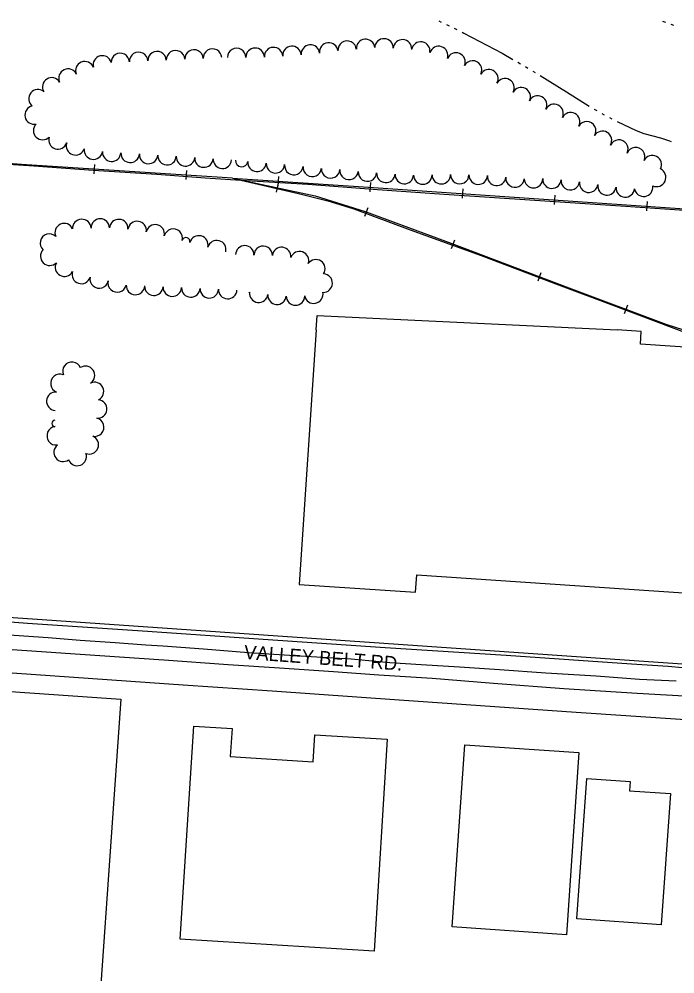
# Model space of a CAD drawing. Extents: x -25029 to 2274964, y -81170 to 687028.
# Drawn here: x -8354 to -7644, y -65446 to -64412 of the extents above; entities that cross this region are included whole.
import ezdxf

# ---------------------------------------------------------------- set-up
doc = ezdxf.new("R2010")
doc.units = 0
for name, color, linetype in [('81911BEA - RW_X_Fee_RW', 7, 'Continuous'), ('BLDG', 7, 'Continuous'), ('GE_X_CL_2000', 7, 'Continuous'), ('PV_X_EOP', 7, 'Continuous'), ('RD_X_RR_1', 7, 'Continuous'), ('ROAD-NAME', 7, 'Continuous'), ('RR', 7, 'Continuous'), ('TREES', 7, 'Continuous'), ('WATER', 7, 'Continuous')]:
    doc.layers.add(name, color=color, linetype=linetype)

msp = doc.modelspace()

# ---------------------------------------------------------------- linework, layer by layer
at = {"layer": '81911BEA - RW_X_Fee_RW'}
for points in [[(-7307.6, -65121.1), (-7510.8, -65119.2), (-8360.2, -65060.1), (-8519.4, -65049), (-8521.8, -65048.8), (-8532.9, -65048.1), (-8559.7, -65046.2), (-8580.6, -65044.7)], [(-7519.6, -65178.7), (-7632.7, -65170.8), (-7750.8, -65162.6), (-7942.6, -65149.3), (-8079.8, -65139.7), (-8176.4, -65133), (-8459.5, -65113.3), (-8523.4, -65108.9), (-8584.7, -65104.6)]]:
    msp.add_lwpolyline(points, dxfattribs=at)
at = {"layer": 'BLDG'}
msp.add_line((-8032.2, -64748.4), (-8050.8, -65024.1), dxfattribs=at)
for points in [[(-8032.2, -64748.4), (-8031.1, -64732.9), (-7706.6, -64748.4)], [(-8050.8, -65024.1), (-7924.8, -65032.6), (-7923.5, -65013.7), (-7549.1, -65039), (-7531.2, -64774.2), (-7681.4, -64764), (-7680.5, -64750.1), (-7706.6, -64748.4)]]:
    msp.add_lwpolyline(points, dxfattribs=at)
for points in [[(-8417, -65456.8), (-8407.3, -65318.9), (-8434.6, -65311), (-8423.7, -65154.7), (-8395.8, -65156.7), (-8394.5, -65137.8), (-8243.7, -65148.4), (-8266.1, -65467.4)], [(-8123.4, -65180), (-8125.3, -65210.5), (-8035.7, -65216.1), (-8033.8, -65186.9), (-7955.3, -65191.8), (-7969.7, -65421.3), (-8179.4, -65408.2), (-8164.9, -65177.4)], [(-7748, -65206.2), (-7761.5, -65403.4), (-7885, -65394.9), (-7871.4, -65197.7)], [(-7692.6, -65237.4), (-7693.3, -65247.4), (-7648.9, -65250.5), (-7659, -65392.7), (-7750.2, -65386.2), (-7739.4, -65234.1)]]:
    msp.add_lwpolyline(points, close=True, dxfattribs=at)
at = {"layer": 'GE_X_CL_2000'}
msp.add_lwpolyline([(-8369.6, -65078.3), (-8322.3, -65081.6), (-8287.8, -65084.4), (-8250, -65086.8), (-8216.5, -65089.4), (-8198.4, -65090.7), (-8154.3, -65093.8), (-8105.5, -65097.7), (-8067.1, -65100.5), (-8025.7, -65102.7), (-7994.6, -65104.7), (-7952.6, -65108.5), (-7918.7, -65110.9), (-7877.1, -65113.3), (-7834, -65116.2), (-7783.6, -65119.7), (-7729.1, -65123.2), (-7682.5, -65126.5), (-7642.7, -65128.3)], dxfattribs=at)
at = {"layer": 'PV_X_EOP'}
for p, q in [((-8344.8, -65066.4), (-8529, -65052.9)), ((-8215, -65075), (-8344.8, -65066.4)), ((-8089.6, -65083.7), (-8215, -65075)), ((-7957.8, -65092.8), (-8089.6, -65083.7)), ((-7826.7, -65101.1), (-7957.8, -65092.8)), ((-7691, -65110.3), (-7826.7, -65101.1)), ((-7651.2, -65113.1), (-7691, -65110.3)), ((-7602.6, -65117.2), (-7651.2, -65113.1))]:
    msp.add_line(p, q, dxfattribs=at)
msp.add_lwpolyline([(-8403.7, -65091.6), (-8287.8, -65099.6), (-8197.2, -65105.9), (-8127.7, -65110.9), (-8072.1, -65114.5), (-8013.6, -65118.5), (-7964.6, -65122), (-7906.9, -65125.6), (-7840.2, -65131.1), (-7764.4, -65136.6), (-7684.9, -65142), (-7621.5, -65145.5), (-7559.7, -65149.8), (-7484.3, -65155.2), (-7432.2, -65158.5), (-7388, -65161), (-7351.4, -65163.6), (-7305.8, -65165.9), (-7268.4, -65168.2), (-7247.9, -65170.1), (-7235.1, -65171.2)], dxfattribs=at)
at = {"layer": 'RD_X_RR_1'}
for points in [[(-9225.8, -64451.8), (-9193.7, -64461.8), (-9157.9, -64472.5), (-9119.3, -64483.5), (-9078.6, -64494.1), (-9033, -64503.8), (-8990.6, -64512), (-8939.1, -64520.7), (-8894.3, -64527.3), (-8849.3, -64533), (-8810.1, -64537.3), (-8760.6, -64541.9), (-8695, -64546.3), (-8649.5, -64549.4), (-8583.3, -64553.9), (-8521.8, -64558.4), (-8454.6, -64562.9), (-8388.1, -64567.8), (-8337.8, -64570.9), (-8273.7, -64575.7), (-8204.8, -64580), (-8152.5, -64583.8), (-8113.8, -64586.5)], [(-8113.8, -64586.5), (-8051.3, -64600.7), (-8019.8, -64608.7), (-7991.6, -64617.5), (-7930.5, -64640), (-7853.7, -64667.9), (-7775.7, -64697.6), (-7702.6, -64725), (-7628.8, -64752.8)], [(-8113.8, -64586.5), (-8041.5, -64590.9), (-7966, -64596.5), (-7893.6, -64601.5), (-7702.8, -64614.3), (-7638.9, -64618.5), (-7582.9, -64622.4), (-7516.3, -64627), (-7442.7, -64632.1), (-7377.5, -64635.9), (-7324.7, -64639.8), (-7243, -64646.2), (-7159.3, -64651.8)]]:
    msp.add_lwpolyline(points, dxfattribs=at)
at = {"layer": 'RR'}
for p, q in [((-8272.4, -64569.4), (-8273.1, -64579.4)), ((-8172.6, -64575.9), (-8173.3, -64585.8)), ((-8075.2, -64599.4), (-8073.1, -64589.6)), ((-8073.5, -64592.4), (-8072.8, -64582.4)), ((-7973.7, -64599.1), (-7973, -64589.1)), ((-7873.9, -64605.9), (-7873.3, -64595.9)), ((-7774.2, -64612.7), (-7773.5, -64602.7)), ((-7674.4, -64619.5), (-7673.7, -64609.6)), ((-7979.5, -64625.5), (-7976, -64616.1)), ((-7885.8, -64660.3), (-7882.3, -64651)), ((-7792.2, -64695.5), (-7788.7, -64686.2)), ((-7698.6, -64730.7), (-7695.1, -64721.4))]:
    msp.add_line(p, q, dxfattribs=at)
for points in [[(-8123, -64584.1), (-8351.4, -64569.3), (-8550.3, -64554.7), (-8738.4, -64541.7), (-8817.7, -64534.7), (-8870.3, -64529.1), (-8945.3, -64518.6), (-9004, -64508.1), (-9104.9, -64485.3), (-9189, -64461.6), (-9278.4, -64432.1), (-9377.8, -64393.2), (-9451.7, -64359.8), (-9555.4, -64306.9), (-9661.5, -64244.3), (-9748.4, -64184.6)], [(-8123, -64584.1), (-7975.6, -64593.9), (-7475.4, -64628.1), (-7223.8, -64646.2), (-7086.9, -64655.4), (-6939.2, -64672.5), (-6864.5, -64686.5), (-6810.8, -64699.4), (-6730.7, -64721.1), (-6647, -64748.4)], [(-8123, -64584.1), (-8033.4, -64603.2), (-7979.4, -64620.2), (-7885.4, -64655.1), (-7758.7, -64702.8), (-7653.9, -64742.2), (-7634.7, -64748.4)]]:
    msp.add_lwpolyline(points, dxfattribs=at)
at = {"layer": 'TREES'}
for centre, radius, start, end in [((-7998.8, -64445.6), 10, 5.0361, 185.0361), ((-7978.8, -64443.8), 10, 5.0304, 185.0304), ((-7958.9, -64443.2), 10, 358.3471, 178.3471), ((-7938.9, -64444.2), 10, 356.1464, 176.1464), ((-8184.5, -64456), 10, 2.5902, 182.5902), ((-8164.5, -64455.1), 10, 2.5902, 182.5902), ((-8144.5, -64454.2), 10, 2.5902, 182.5902), ((-8118.4, -64453.5), 10, 359.5944, 179.5944), ((-8098.4, -64453.3), 10, 1.2867, 181.2867), ((-8078.4, -64452.6), 10, 3.2117, 183.2117), ((-8058.5, -64451.3), 10, 3.8432, 183.8432), ((-8038.5, -64449.7), 10, 5.3088, 185.3088), ((-8018.6, -64447.6), 10, 6.7123, 186.7123), ((-7919.1, -64446.6), 10, 350.3329, 170.3329), ((-7899.7, -64451.4), 10, 341.4546, 161.4546), ((-8263.8, -64461.6), 10, 14.2942, 194.2942), ((-8244.3, -64458.7), 9.82, 2.5902, 182.5902), ((-8224.5, -64457.8), 10, 2.5902, 182.5902), ((-8204.5, -64456.9), 10, 2.5902, 182.5902), ((-7881, -64458.5), 10, 337.0983, 157.0983), ((-8301, -64475.9), 10, 25.0618, 205.0618), ((-8282.7, -64467.9), 10, 22.3729, 202.3729), ((-7863, -64467.1), 10, 331.9484, 151.9484), ((-7845.4, -64476.6), 10, 331.2605, 151.2605), ((-8318.6, -64485.4), 10, 31.463, 211.463), ((-7827.9, -64486.3), 10, 330.538, 150.538), ((-7810.4, -64495.9), 10, 332.4164, 152.4164), ((-8333.4, -64498.3), 10, 50.8821, 230.8821), ((-7792.6, -64505.1), 10, 332.6236, 152.6236), ((-8337.6, -64515.9), 10, 102.1834, 282.1834), ((-7774.8, -64514.1), 10, 333.8801, 153.8801), ((-7756.9, -64523.2), 10, 332.2957, 152.2957), ((-8328.4, -64532.7), 10, 135.4354, 315.4354), ((-7739.5, -64533), 10, 328.6459, 148.6459), ((-7722.4, -64543.3), 10, 329.4119, 149.4119), ((-8311.8, -64542.9), 10, 161.4726, 341.4726), ((-8292.8, -64549.2), 10, 161.684, 341.684), ((-7704.7, -64552.7), 10, 334.461, 154.461), ((-8273.4, -64553.9), 10, 171.0113, 351.0113), ((-8253.6, -64556.1), 10, 176.3288, 356.3288), ((-8233.6, -64557.4), 10, 176.3288, 356.3288), ((-8213.7, -64558.6), 10, 176.3288, 356.3288), ((-8193.7, -64559.9), 10, 176.3288, 356.3288), ((-7686.5, -64561), 10, 336.6182, 156.6182), ((-7668.5, -64569.6), 10, 332.0775, 152.0775), ((-8173.7, -64561.2), 10, 176.3288, 356.3288), ((-8153.8, -64562.5), 10, 176.3288, 356.3288), ((-8133.8, -64563.8), 10, 176.3288, 356.3288), ((-8112.9, -64565.4), 6.63, 173.7911, 353.7911), ((-8096.3, -64567.1), 10, 174.9216, 354.9216), ((-8076.4, -64568.7), 10, 175.4854, 355.4854), ((-8056.5, -64570.6), 10, 173.7291, 353.7291), ((-8036.6, -64572.6), 10, 174.66, 354.66), ((-8016.6, -64574.2), 10, 176.5368, 356.5368), ((-7996.7, -64575.8), 10, 174.0214, 354.0214), ((-7976.8, -64577.6), 10, 175.6263, 355.6263), ((-7956.9, -64579.1), 10, 175.9516, 355.9516), ((-7936.9, -64580.3), 10, 176.8725, 356.8725), ((-7896.9, -64580.5), 10, 181.5983, 1.5983), ((-7876.9, -64580.4), 10, 179.0565, 359.0565), ((-7663.8, -64583.4), 10, 245.4744, 65.4744), ((-7916.9, -64580.8), 10, 180.3727, 0.3727), ((-7856.9, -64581), 10, 177.4044, 357.4044), ((-7837, -64582.3), 10, 174.746, 354.746), ((-7817.1, -64584.1), 10, 175.0287, 355.0287), ((-7797.1, -64584.8), 10, 180.7976, 0.7976), ((-7777.1, -64585.3), 10, 176.4179, 356.4179), ((-7757.2, -64587), 10, 173.8861, 353.8861), ((-7737.4, -64589.7), 10, 170.9041, 350.9041), ((-7717.6, -64592.6), 10, 172.2738, 352.2738), ((-7697.7, -64594.8), 10, 175.2372, 355.2372), ((-7677.9, -64594.1), 10, 188.8934, 8.8934), ((-8286, -64638.7), 10, 2.5263, 182.5263), ((-8266, -64638.2), 10, 0.2184, 180.2184), ((-8246, -64638.8), 10, 356.3463, 176.3463), ((-8226.1, -64640.9), 10, 351.6433, 171.6433), ((-8305.1, -64643.2), 10, 24.2284, 204.2284), ((-8206.5, -64644.5), 10, 347.4226, 167.4226), ((-8187, -64649.2), 10, 345.383, 165.383), ((-8321.1, -64654.6), 10, 46.567, 226.567), ((-8173.2, -64652.9), 4.34, 345.2306, 165.2306), ((-8159.3, -64656.5), 10, 345.2306, 165.2306), ((-8139.9, -64661.6), 10, 345.2306, 165.2306), ((-8320.7, -64668.8), 10, 135.9881, 315.9881), ((-8109.6, -64667.2), 10, 358.6295, 178.6295), ((-8089.6, -64667.7), 10, 358.8178, 178.8178), ((-8069.7, -64669), 10, 353.3106, 173.3106), ((-8050.3, -64673.5), 10, 340.7394, 160.7394), ((-8032.6, -64682.3), 10, 326.3804, 146.3804), ((-8304.8, -64680.6), 10, 150.9378, 330.9378), ((-8286.6, -64688.5), 10, 162.241, 342.241), ((-8267.2, -64693.4), 10, 169.2198, 349.2198), ((-8024.7, -64697.9), 10, 267.6682, 87.6682), ((-8247.7, -64697.7), 10, 166.4408, 346.4408), ((-8227.9, -64700.4), 10, 177.4459, 357.4459), ((-8208, -64701.3), 10, 177.4459, 357.4459), ((-8188, -64702.2), 10, 177.4459, 357.4459), ((-8168, -64703.1), 10, 177.4459, 357.4459), ((-8148, -64704), 10, 177.4459, 357.4459), ((-8128, -64704.9), 10, 177.4459, 357.4459), ((-8104.8, -64707.6), 0.364, 172.6183, 352.6183), ((-8094.5, -64708.9), 10, 172.7016, 352.7016), ((-8074.6, -64711), 10, 175.0842, 355.0842), ((-8054.7, -64711.8), 10, 180.2176, 0.2176), ((-8034.9, -64709.8), 10, 191.4089, 11.4089), ((-8296.7, -64793.3), 10, 22.8898, 202.8898), ((-8309.7, -64806.5), 10, 68.3483, 248.3483), ((-8282, -64797.7), 10, 303.6107, 123.6107), ((-8272.2, -64815.1), 10, 295.1862, 115.1862), ((-8314.1, -64825.8), 10, 85.3645, 265.3645), ((-8268.9, -64834.1), 10, 264.4161, 84.4161), ((-8315, -64849.8), 3.49, 90, 270), ((-8272, -64853.8), 10, 257.6425, 77.6425), ((-8313.7, -64863.2), 10, 97.3514, 277.3514), ((-8277.8, -64872.9), 10, 248.5706, 68.5706), ((-8306.3, -64881.1), 10, 127.2172, 307.2172), ((-8290.9, -64885.6), 10, 199.8333, 19.8333)]:
    msp.add_arc(centre, radius, start, end, dxfattribs=at)
at = {"layer": 'WATER'}
for p, q in [((-7899.7, -64413.9), (-7896.9, -64415.2)), ((-7657.3, -64414.1), (-7654.3, -64415.2)), ((-7891.3, -64418), (-7888.4, -64419.3)), ((-7882.8, -64422), (-7880, -64423.4)), ((-7648.5, -64417.4), (-7645.6, -64418.5)), ((-7813.9, -64458.8), (-7811.2, -64460.3)), ((-7805.8, -64463.5), (-7803.1, -64465)), ((-7797.7, -64468.3), (-7795.1, -64469.9)), ((-7731.3, -64509.5), (-7728.7, -64511.1)), ((-7723.2, -64514.2), (-7720.5, -64515.6)), ((-7714.9, -64518.5), (-7712.2, -64519.9))]:
    msp.add_line(p, q, dxfattribs=at)
for points in [[(-7874.4, -64426.1), (-7872.4, -64427.1), (-7831, -64448.8), (-7819.3, -64455.6)], [(-7789.8, -64473.2), (-7761.5, -64490.8), (-7736.7, -64506.2)], [(-7706.6, -64522.7), (-7686.1, -64532.5), (-7677.5, -64535.8), (-7659.5, -64540.6), (-7649.8, -64543.8), (-7648.2, -64544.5)]]:
    msp.add_lwpolyline(points, dxfattribs=at)

# ---------------------------------------------------------------- texts
at = {"layer": 'ROAD-NAME'}
msp.add_text('VALLEY BELT RD.', height=15, rotation=355.7201, dxfattribs=at).set_placement((-8110.8, -65104.7))

doc.saveas('drawing.dxf')
